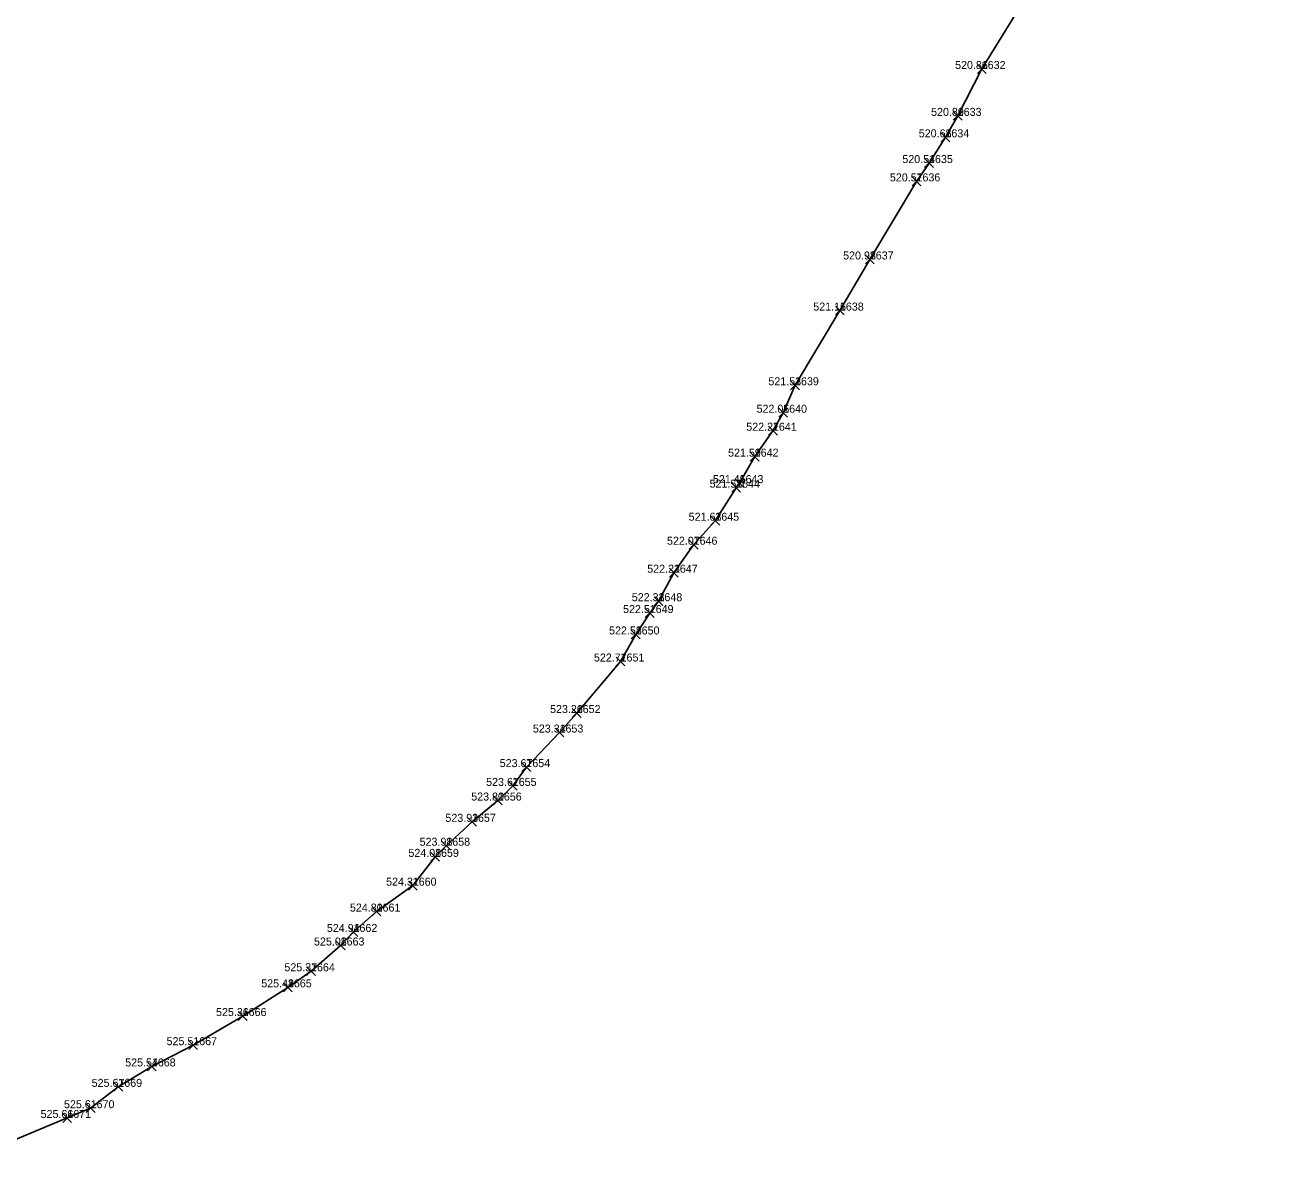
# Model space of a CAD drawing. Extents: x -874041 to -866452, y -1055592 to -1049889.
# Drawn here: x -873329.2 to -873172.8, y -1055553.5 to -1055412.6 of the extents above; entities that cross this region are included whole.
import ezdxf

# ---------------------------------------------------------------- set-up
doc = ezdxf.new("R2010")
doc.units = 0
for name, color, linetype in [('Vrstva 32', 7, 'Continuous'), ('Vrstva 60', 7, 'Continuous'), ('Vrstva 61', 7, 'Continuous')]:
    doc.layers.add(name, color=color, linetype=linetype)

msp = doc.modelspace()

# ---------------------------------------------------------------- linework, layer by layer
at = {"layer": 'Vrstva 32'}
for points in [[(-873172.75, -1055355.36), (-873174.08, -1055358.11), (-873177.47, -1055363.85), (-873180.92, -1055369.11), (-873185.51, -1055377.43), (-873189.85, -1055384.95), (-873191.55, -1055387.13), (-873194.09, -1055391.21), (-873195.62, -1055394.44), (-873196.65, -1055396.26), (-873200.6, -1055402.92), (-873201.9, -1055404.96), (-873203.17, -1055407.6), (-873209.64, -1055418.14), (-873212.64, -1055424), (-873214.18, -1055426.68), (-873216.23, -1055429.9), (-873217.79, -1055432.19), (-873223.63, -1055441.95), (-873227.36, -1055448.34), (-873232.97, -1055457.68)], [(-873232.97, -1055457.68), (-873234.45, -1055461.11), (-873235.73, -1055463.36), (-873238.01, -1055466.6), (-873239.9, -1055469.91), (-873240.32, -1055470.48), (-873242.93, -1055474.61), (-873245.64, -1055477.61), (-873248.11, -1055481.11), (-873250.04, -1055484.67), (-873251.13, -1055486.15), (-873252.88, -1055488.83), (-873254.77, -1055492.21), (-873260.25, -1055498.65), (-873262.4, -1055501.09), (-873266.54, -1055505.41), (-873268.24, -1055507.76), (-873270.1, -1055509.59), (-873273.33, -1055512.25), (-873276.55, -1055515.24), (-873277.95, -1055516.63), (-873280.74, -1055520.23), (-873285.26, -1055523.47), (-873288.14, -1055526.02), (-873289.75, -1055527.71), (-873293.45, -1055530.93), (-873296.34, -1055532.94), (-873301.99, -1055536.53), (-873308.17, -1055540.17), (-873313.34, -1055542.83), (-873317.53, -1055545.38), (-873320.99, -1055548.05), (-873323.91, -1055549.27), (-873334.09, -1055553.52)]]:
    msp.add_lwpolyline(points, dxfattribs=at)
at = {"layer": 'Vrstva 60'}
for p, q in [((-873210.19, -1055418.69), (-873209.09, -1055417.59)), ((-873209.09, -1055418.69), (-873210.19, -1055417.59)), ((-873213.19, -1055424.55), (-873212.09, -1055423.45)), ((-873212.09, -1055424.55), (-873213.19, -1055423.45)), ((-873214.73, -1055427.23), (-873213.63, -1055426.13)), ((-873213.63, -1055427.23), (-873214.73, -1055426.13)), ((-873216.78, -1055430.45), (-873215.68, -1055429.35)), ((-873215.68, -1055430.45), (-873216.78, -1055429.35)), ((-873218.34, -1055432.74), (-873217.24, -1055431.64)), ((-873217.24, -1055432.74), (-873218.34, -1055431.64)), ((-873224.18, -1055442.5), (-873223.08, -1055441.4)), ((-873223.08, -1055442.5), (-873224.18, -1055441.4)), ((-873227.91, -1055448.89), (-873226.81, -1055447.79)), ((-873226.81, -1055448.89), (-873227.91, -1055447.79)), ((-873233.52, -1055458.23), (-873232.42, -1055457.13)), ((-873232.42, -1055458.23), (-873233.52, -1055457.13)), ((-873235, -1055461.66), (-873233.9, -1055460.56)), ((-873233.9, -1055461.66), (-873235, -1055460.56)), ((-873236.28, -1055463.91), (-873235.18, -1055462.81)), ((-873235.18, -1055463.91), (-873236.28, -1055462.81)), ((-873238.56, -1055467.15), (-873237.46, -1055466.05)), ((-873237.46, -1055467.15), (-873238.56, -1055466.05)), ((-873240.45, -1055470.46), (-873239.35, -1055469.36)), ((-873239.35, -1055470.46), (-873240.45, -1055469.36)), ((-873240.87, -1055471.03), (-873239.77, -1055469.93)), ((-873239.77, -1055471.03), (-873240.87, -1055469.93)), ((-873243.48, -1055475.16), (-873242.38, -1055474.06)), ((-873242.38, -1055475.16), (-873243.48, -1055474.06)), ((-873246.19, -1055478.16), (-873245.09, -1055477.06)), ((-873245.09, -1055478.16), (-873246.19, -1055477.06)), ((-873248.66, -1055481.66), (-873247.56, -1055480.56)), ((-873247.56, -1055481.66), (-873248.66, -1055480.56)), ((-873250.59, -1055485.22), (-873249.49, -1055484.12)), ((-873249.49, -1055485.22), (-873250.59, -1055484.12)), ((-873251.68, -1055486.7), (-873250.58, -1055485.6)), ((-873250.58, -1055486.7), (-873251.68, -1055485.6)), ((-873253.43, -1055489.38), (-873252.33, -1055488.28)), ((-873252.33, -1055489.38), (-873253.43, -1055488.28)), ((-873255.32, -1055492.76), (-873254.22, -1055491.66)), ((-873254.22, -1055492.76), (-873255.32, -1055491.66)), ((-873260.8, -1055499.2), (-873259.7, -1055498.1)), ((-873259.7, -1055499.2), (-873260.8, -1055498.1)), ((-873262.95, -1055501.64), (-873261.85, -1055500.54)), ((-873261.85, -1055501.64), (-873262.95, -1055500.54)), ((-873267.09, -1055505.96), (-873265.99, -1055504.86)), ((-873265.99, -1055505.96), (-873267.09, -1055504.86)), ((-873268.79, -1055508.31), (-873267.69, -1055507.21)), ((-873267.69, -1055508.31), (-873268.79, -1055507.21)), ((-873270.65, -1055510.14), (-873269.55, -1055509.04)), ((-873269.55, -1055510.14), (-873270.65, -1055509.04)), ((-873273.88, -1055512.8), (-873272.78, -1055511.7)), ((-873272.78, -1055512.8), (-873273.88, -1055511.7)), ((-873277.1, -1055515.79), (-873276, -1055514.69)), ((-873276, -1055515.79), (-873277.1, -1055514.69)), ((-873278.5, -1055517.18), (-873277.4, -1055516.08)), ((-873277.4, -1055517.18), (-873278.5, -1055516.08)), ((-873281.29, -1055520.78), (-873280.19, -1055519.68)), ((-873280.19, -1055520.78), (-873281.29, -1055519.68)), ((-873285.81, -1055524.02), (-873284.71, -1055522.92)), ((-873284.71, -1055524.02), (-873285.81, -1055522.92)), ((-873288.69, -1055526.57), (-873287.59, -1055525.47)), ((-873287.59, -1055526.57), (-873288.69, -1055525.47)), ((-873290.3, -1055528.26), (-873289.2, -1055527.16)), ((-873289.2, -1055528.26), (-873290.3, -1055527.16)), ((-873294, -1055531.48), (-873292.9, -1055530.38)), ((-873292.9, -1055531.48), (-873294, -1055530.38)), ((-873296.89, -1055533.49), (-873295.79, -1055532.39)), ((-873295.79, -1055533.49), (-873296.89, -1055532.39)), ((-873302.54, -1055537.08), (-873301.44, -1055535.98)), ((-873301.44, -1055537.08), (-873302.54, -1055535.98)), ((-873308.72, -1055540.72), (-873307.62, -1055539.62)), ((-873307.62, -1055540.72), (-873308.72, -1055539.62)), ((-873313.89, -1055543.38), (-873312.79, -1055542.28)), ((-873312.79, -1055543.38), (-873313.89, -1055542.28)), ((-873318.08, -1055545.93), (-873316.98, -1055544.83)), ((-873316.98, -1055545.93), (-873318.08, -1055544.83)), ((-873321.54, -1055548.6), (-873320.44, -1055547.5)), ((-873320.44, -1055548.6), (-873321.54, -1055547.5)), ((-873324.46, -1055549.82), (-873323.36, -1055548.72)), ((-873323.36, -1055549.82), (-873324.46, -1055548.72))]:
    msp.add_line(p, q, dxfattribs=at)

# ---------------------------------------------------------------- texts
for s, p in [('1632', (-873209.64, -1055418.14)), ('1633', (-873212.64, -1055424)), ('1634', (-873214.18, -1055426.68)), ('1635', (-873216.23, -1055429.9)), ('1636', (-873217.79, -1055432.19)), ('1637', (-873223.63, -1055441.95)), ('1638', (-873227.36, -1055448.34)), ('1639', (-873232.97, -1055457.68)), ('1640', (-873234.45, -1055461.11)), ('1641', (-873235.73, -1055463.36)), ('1642', (-873238.01, -1055466.6)), ('1644', (-873240.32, -1055470.48)), ('1643', (-873239.9, -1055469.91)), ('1645', (-873242.93, -1055474.61)), ('1646', (-873245.64, -1055477.61)), ('1647', (-873248.11, -1055481.11)), ('1648', (-873250.04, -1055484.67)), ('1649', (-873251.13, -1055486.15)), ('1650', (-873252.88, -1055488.83)), ('1651', (-873254.77, -1055492.21)), ('1652', (-873260.25, -1055498.65)), ('1653', (-873262.4, -1055501.09)), ('1654', (-873266.54, -1055505.41)), ('1655', (-873268.24, -1055507.76)), ('1656', (-873270.1, -1055509.59)), ('1657', (-873273.33, -1055512.25)), ('1658', (-873276.55, -1055515.24)), ('1659', (-873277.95, -1055516.63)), ('1660', (-873280.74, -1055520.23)), ('1661', (-873285.26, -1055523.47)), ('1662', (-873288.14, -1055526.02)), ('1663', (-873289.75, -1055527.71)), ('1664', (-873293.45, -1055530.93)), ('1665', (-873296.34, -1055532.94)), ('1666', (-873301.99, -1055536.53)), ('1667', (-873308.17, -1055540.17)), ('1668', (-873313.34, -1055542.83)), ('1669', (-873317.53, -1055545.38)), ('1670', (-873320.99, -1055548.05)), ('1671', (-873323.91, -1055549.27))]:
    msp.add_text(s, height=1, dxfattribs=at).set_placement(p)
at = {"layer": 'Vrstva 61'}
for s, p in [('520.86 ', (-873212.97, -1055418.14)), ('520.80 ', (-873215.97, -1055424)), ('520.68 ', (-873217.51, -1055426.68)), ('520.54 ', (-873219.56, -1055429.9)), ('520.57 ', (-873221.12, -1055432.19)), ('520.98 ', (-873226.96, -1055441.95)), ('521.15 ', (-873230.69, -1055448.34)), ('521.53 ', (-873236.3, -1055457.68)), ('522.05 ', (-873237.78, -1055461.11)), ('522.27 ', (-873239.06, -1055463.36)), ('521.59 ', (-873241.34, -1055466.6)), ('521.58 ', (-873243.65, -1055470.48)), ('521.45 ', (-873243.23, -1055469.91)), ('521.63 ', (-873246.26, -1055474.61)), ('522.07 ', (-873248.97, -1055477.61)), ('522.23 ', (-873251.44, -1055481.11)), ('522.33 ', (-873253.37, -1055484.67)), ('522.51 ', (-873254.46, -1055486.15)), ('522.58 ', (-873256.21, -1055488.83)), ('522.77 ', (-873258.1, -1055492.21)), ('523.26 ', (-873263.58, -1055498.65)), ('523.34 ', (-873265.73, -1055501.09)), ('523.67 ', (-873269.87, -1055505.41)), ('523.67 ', (-873271.57, -1055507.76)), ('523.80 ', (-873273.43, -1055509.59)), ('523.93 ', (-873276.66, -1055512.25)), ('523.98 ', (-873279.88, -1055515.24)), ('524.08 ', (-873281.28, -1055516.63)), ('524.31 ', (-873284.07, -1055520.23)), ('524.80 ', (-873288.59, -1055523.47)), ('524.94 ', (-873291.47, -1055526.02)), ('525.08 ', (-873293.08, -1055527.71)), ('525.37 ', (-873296.78, -1055530.93)), ('525.48 ', (-873299.67, -1055532.94)), ('525.36 ', (-873305.32, -1055536.53)), ('525.51 ', (-873311.5, -1055540.17)), ('525.54 ', (-873316.67, -1055542.83)), ('525.67 ', (-873320.86, -1055545.38)), ('525.61 ', (-873324.32, -1055548.05)), ('525.66 ', (-873327.24, -1055549.27))]:
    msp.add_text(s, height=1, dxfattribs=at).set_placement(p)

doc.saveas('drawing.dxf')
